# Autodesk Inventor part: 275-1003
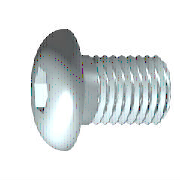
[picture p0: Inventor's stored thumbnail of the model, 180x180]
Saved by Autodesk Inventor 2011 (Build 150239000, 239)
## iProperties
IsCustomPart: 0
Company: Autodesk Inc.
Created: 2010-02
Part Number: 275-1003
Material: Steel, Mild
Description: Hexagon Socket Button Head Cap Screw
Document SubType Name: Modeling
Standard: ANSI B18.3
Designer: Autodesk Inc.
Standard Revision: 2003
Standards Organization: ANSI
Language: en-US
Size Designation: 8 - 32 x 3/8
Categories: <MemberInstance><Categories><Category DisplayName="Fasteners" InternalName="e4da775c-781d-43d5-af7c-5136215cf5a6" Mnemonic="FSTN"><Category DisplayName="Bolts"
Density: 1 g/cm^3
Catalog Web Link: http://www.vexrobotics.com/screws-8-32.html
Vendor: Innovation First, Inc.
Author: Autodesk Inc.
Title: VEX Robotics Kit of Parts
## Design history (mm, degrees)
workplane "Work Plane1"
fillet "Fillet2" dims "d30" = 0.1 (= R)
revolve "Body" stored, may be unused: angle "d10" = 90 deg
sketch "Sketch2"
  geometry: L1 (0, -5.547)-(0, 5.547) reference; L2 (-5.547, 0)-(5.547, 0) reference; L3 (1.378, 0)-(0.689, -1.194); L4 (0.689, -1.194)-(-0.689, -1.194); L5 (-0.689, -1.194)-(-1.378, 0); L6 (-1.378, 0)-(-0.689, 1.194); L7 (-0.689, 1.194)-(0.689, 1.194); L8 (0.689, 1.194)-(1.378, 0); 2 further points
  constraints: 12 end point, 1 coincident, 1 horizontal alignment, 1 point on line, 12 other
extrude "Slot" join sketch "Sketch2" stored distance "d11" = 10; taper "d12" = 0 deg
body "Solid1"
fillet "Fillet1" dims "d17" = 1.9558 (= RR)
feature "Thread" dims "d13" = 7.93476 (= GEL), "d14" = 0
chamfer "Chamfer1" distance "d15" = 0.48692 (= -0.5 x SPD + 0.5 x GD); stored, may be unused: second distance "d16" = 0.48692 (= GUL), angle "d27" = 45 deg
sketch "Sketch1"
  geometry: L1 (-0.093, 0)-(9.525, 0); L2 (9.525, 0)-(9.525, 2.083); L3 (9.525, 2.083)-(1.59, 2.083); L4 (1.59, 2.083)-(0, 2.083); L5 (0, 2.083)-(0, 2.083); L6 (0, 2.083)-(0, 3.962); L7 (0, 3.962)-(-2.21, 3.962); L8 (-2.21, 3.962)-(-2.21, 1.378); L9 (-2.21, 1.378)-(-0.889, 1.378); L10 (-0.889, 1.378)-(-0.093, 0); L11 (-4.557, 0)-(11.872, 0) reference; L12 (0, -0.792)-(0, 4.755) reference; L13 (1.59, 2.083)-(0, 2.083)
  constraints: 22 end point, 6 parallel, 2 collinear, 2 perpendicular, 1 horizontal, 1 point on line
  dimensions: "d1" = 7.93476 distance from line of L3.end L2 (= GEL); "d2" = 1.59014 distance of L4.end L3.end (computed from GAL); "d3" = 2.2098 distance between parallel lines of L8 L6 (= KOH); "d4" = 1.3208 distance of L8.end L9.end (= INTI); "d5" = 60 deg angle of L10 L1; "d6" = 4.1656 diameter of L3 L1 (= GD); "d7" = 4.1656 diameter of L5 L1 (= BDM); "d8" = 2.75696 diameter of L9 L1 (= 1.1547 x SW); "d9" = 7.9248 diameter of L7 L1 (= KOD); "d26" = 9.525 distance between parallel lines of L12 L2 (= NLG)
other parameters: "GD" = 4.1656 (= NND) [user parameter; used in 2 equation terms], "NLG" = 9.525 [user parameter; used in 1 equation term], "GEL" = 7.93476 [user parameter; used in 2 equation terms], "KOD" = 7.9248 [user parameter; used in 1 equation term], "KOH" = 2.2098 [user parameter; used in 1 equation term], "INTI" = 1.3208 [user parameter; used in 1 equation term], "GAL" = 1.59004 [user parameter; used in 1 equation term], "GUL" = 0.48692 [user parameter; used in 1 equation term], "BDM" = 4.1656 (= NND) [user parameter; used in 1 equation term], "SW" = 2.3876 [user parameter; used in 1 equation term], "RR" = 1.9558 [user parameter; used in 1 equation term], "SPD" = 3.19176 [user parameter; used in 2 equation terms], "d19" = 0, "d28" = 0, "d29" = 0, "R" = 0.1 [user parameter; used in 1 equation term], "TOA" = 30 deg [user parameter], "GD1" = 3.19176 (= SPD) [user parameter], "THREADDIA" = 4.1656 [user parameter], "PTC" = 0.79375 (computed from TPU) [user parameter], "KOH1" = 0.381 [user parameter], "NND" = 4.1656 [user parameter; used in 2 equation terms], "E0" = 2.75768 [user parameter]
